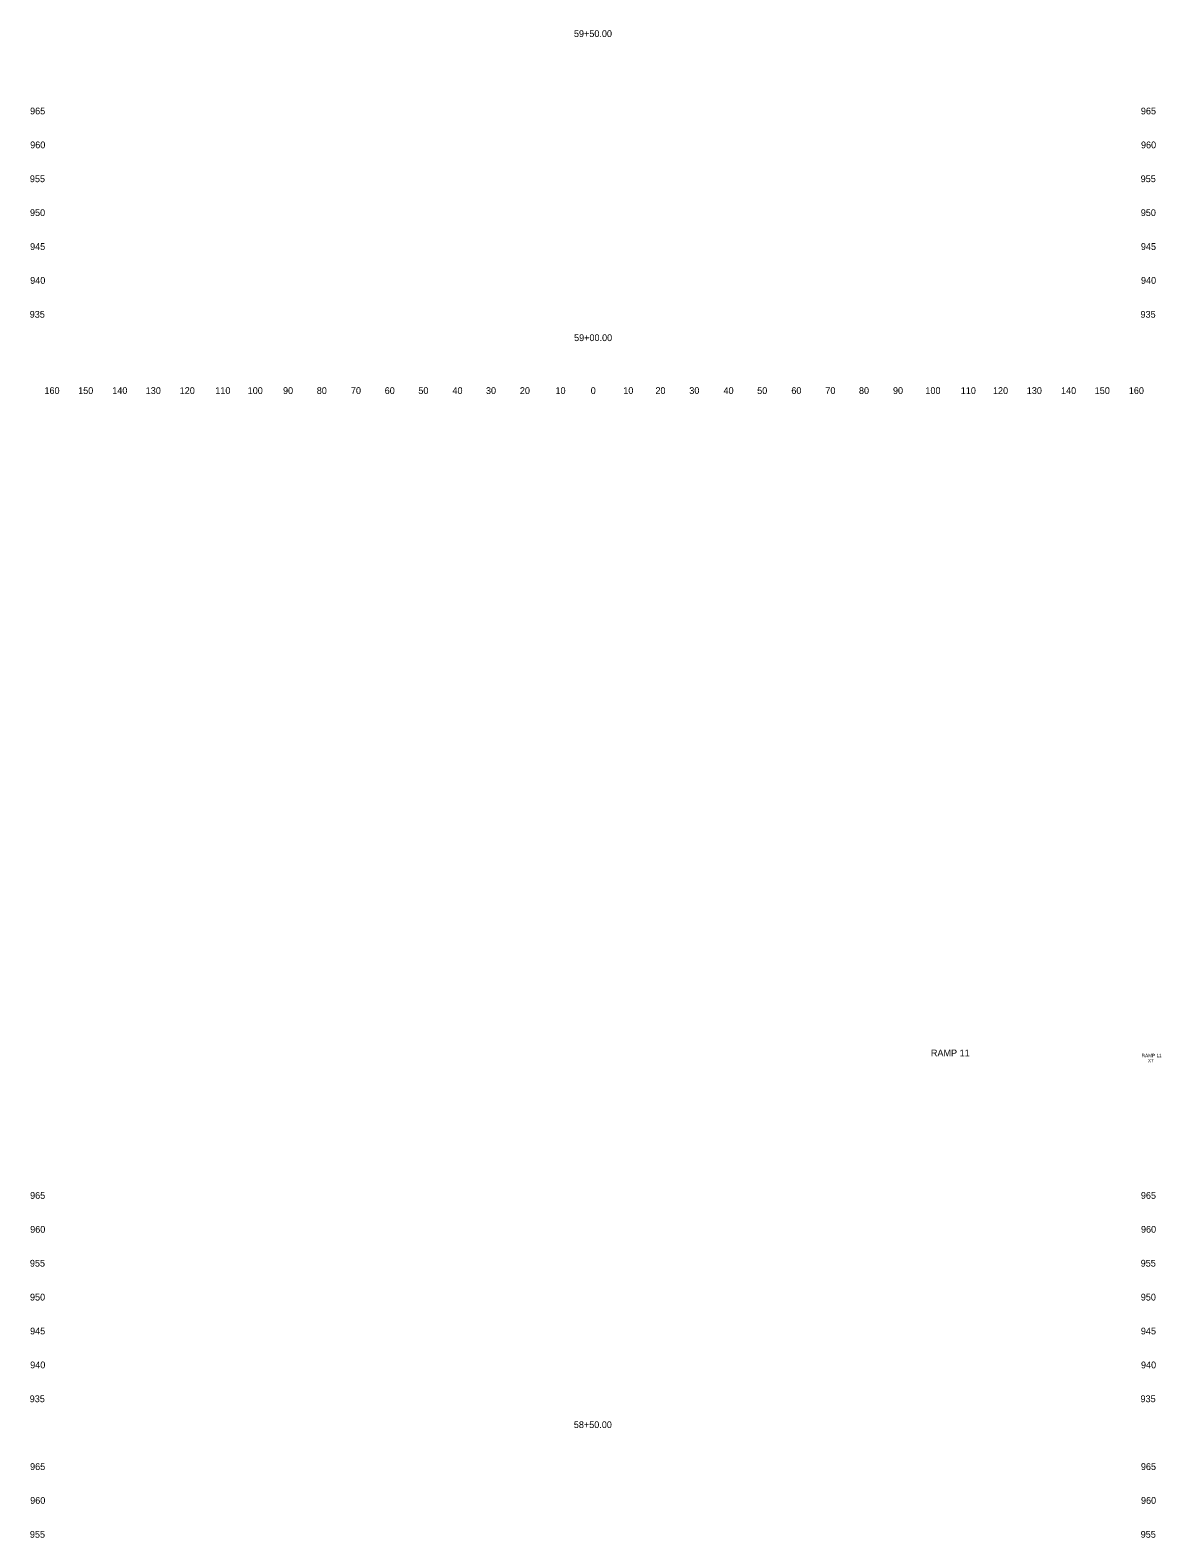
# Model space of a CAD drawing. Extents: x 4994 to 5843, y 4997 to 8804.
# Drawn here: x 4993.9 to 5327.6, y 7460 to 7904.9 of the extents above; entities that cross this region are included whole.
import ezdxf

# ---------------------------------------------------------------- set-up
doc = ezdxf.new("R2010")
doc.units = 0
for name, color, linetype in [('RD_SHT_ID', 7, 'Continuous'), ('RD_XS_TX_Offset', 7, 'Continuous'), ('RD_XS_TX_Station', 7, 'Continuous')]:
    doc.layers.add(name, color=color, linetype=linetype)

msp = doc.modelspace()

# ---------------------------------------------------------------- texts
at = {"layer": 'RD_SHT_ID'}
for s, height, p in [('RAMP 11', 2, (5259.69, 7602.06)), ('RAMP 11', 1, (5321.89, 7601.8)), ('X7', 1, (5323.74, 7600.3))]:
    msp.add_text(s, height=height, dxfattribs=at).set_placement(p)
at = {"layer": 'RD_XS_TX_Offset'}
for s, p in [('965', (4993.86, 7880)), ('965', (5321.66, 7880)), ('960', (4993.89, 7870)), ('960', (5321.69, 7870)), ('955', (4993.8, 7860)), ('955', (5321.6, 7860)), ('950', (4993.83, 7850)), ('950', (5321.63, 7850)), ('945', (4993.86, 7840)), ('945', (5321.66, 7840)), ('940', (4993.89, 7830)), ('940', (5321.69, 7830)), ('935', (4993.75, 7820)), ('935', (5321.55, 7820)), ('160', (4998.1, 7797.5)), ('150', (5008.04, 7797.5)), ('140', (5018.1, 7797.5)), ('130', (5027.99, 7797.5)), ('120', (5038.01, 7797.5)), ('110', (5048.51, 7797.5)), ('100', (5058.07, 7797.5)), ('90', (5068.5, 7797.5)), ('80', (5078.46, 7797.5)), ('70', (5088.54, 7797.5)), ('60', (5098.5, 7797.5)), ('50', (5108.43, 7797.5)), ('40', (5118.5, 7797.5)), ('30', (5128.39, 7797.5)), ('20', (5138.4, 7797.5)), ('10', (5148.91, 7797.5)), ('0', (5159.3, 7797.5)), ('0', (5159.3, 7797.5)), ('10', (5168.91, 7797.5)), ('20', (5178.4, 7797.5)), ('30', (5188.39, 7797.5)), ('40', (5198.5, 7797.5)), ('50', (5208.43, 7797.5)), ('60', (5218.5, 7797.5)), ('70', (5228.54, 7797.5)), ('80', (5238.46, 7797.5)), ('90', (5248.5, 7797.5)), ('100', (5258.07, 7797.5)), ('110', (5268.51, 7797.5)), ('120', (5278.01, 7797.5)), ('130', (5287.99, 7797.5)), ('140', (5298.1, 7797.5)), ('150', (5308.04, 7797.5)), ('160', (5318.1, 7797.5)), ('965', (4993.86, 7560)), ('965', (5321.66, 7560)), ('960', (4993.89, 7550)), ('960', (5321.69, 7550)), ('955', (4993.8, 7540)), ('955', (5321.6, 7540)), ('950', (4993.83, 7530)), ('950', (5321.63, 7530)), ('945', (4993.86, 7520)), ('945', (5321.66, 7520)), ('940', (4993.89, 7510)), ('940', (5321.69, 7510)), ('935', (4993.75, 7500)), ('935', (5321.55, 7500)), ('965', (4993.86, 7480)), ('965', (5321.66, 7480)), ('960', (4993.89, 7470)), ('960', (5321.69, 7470)), ('955', (4993.8, 7460)), ('955', (5321.6, 7460))]:
    msp.add_text(s, height=2, dxfattribs=at).set_placement(p)
at = {"layer": 'RD_XS_TX_Station'}
for s, p in [('59+50.00', (5154.35, 7902.82)), ('59+00.00', (5154.39, 7813.1)), ('58+50.00', (5154.32, 7492.36))]:
    msp.add_text(s, height=2, dxfattribs=at).set_placement(p)

doc.saveas('drawing.dxf')
